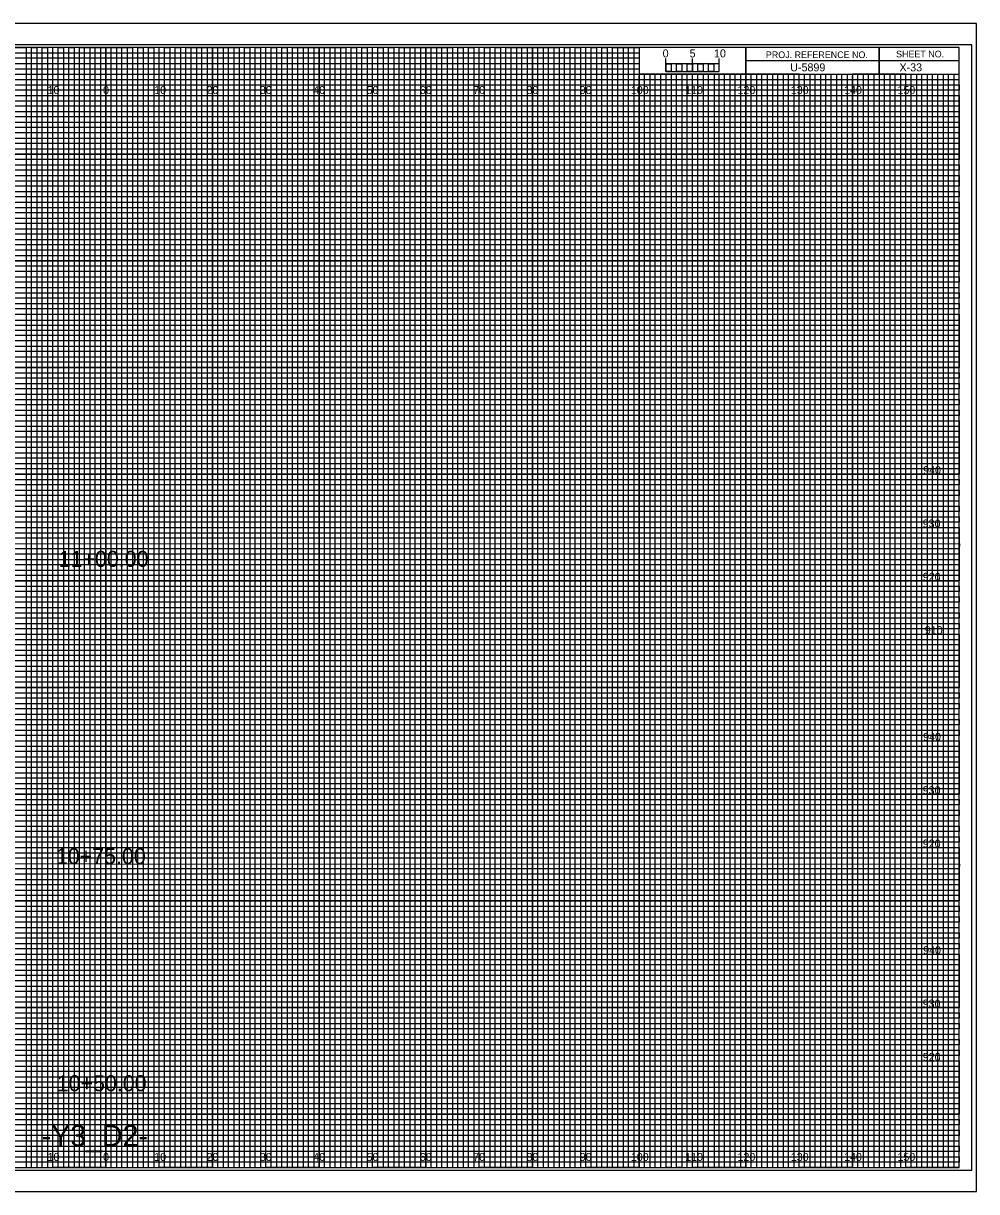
# Model space of a CAD drawing. Extents: x -13 to 323, y -4 to 214.
# Drawn here: x 144.5 to 323.3, y -4.5 to 214.5 of the extents above; entities that cross this region are included whole.
import ezdxf

# ---------------------------------------------------------------- set-up
doc = ezdxf.new("R2010")
doc.units = 0
for name, color, linetype in [('Prop XS Alignment Label', 7, 'Continuous'), ('Prop XS Bar Scale Labels', 7, 'Continuous'), ('Prop XS Elevation Labels', 7, 'Continuous'), ('Prop XS Offset Labels', 7, 'Continuous'), ('Prop XS Project Number', 7, 'Continuous'), ('Prop XS Sheet Number', 7, 'Continuous'), ('Prop XS Station Labels', 7, 'Continuous'), ('Sheet Cross Section CELL', 7, 'Continuous'), ('Sheet Cross Section Grid Major CELL', 7, 'Continuous'), ('Sheet Cross Section Grid Middle CELL', 7, 'Continuous'), ('Sheet Cross Section Grid Minor 1 CELL', 7, 'Continuous'), ('Sheet Cross Section Grid Minor 2 CELL', 7, 'Continuous'), ('Sheet Cross Section Scale CELL', 7, 'Continuous'), ('Sheet Cutting Line CELL', 7, 'Continuous'), ('Sheet DOT Grid CELL', 7, 'Continuous'), ('Sheet Plot Border Inside CELL', 7, 'Continuous'), ('Sheet Plot Border Outside CELL', 7, 'Continuous')]:
    doc.layers.add(name, color=color, linetype=linetype)

msp = doc.modelspace()

# ---------------------------------------------------------------- linework, layer by layer
at = {"layer": 'Sheet Cross Section CELL'}
for p, q in [((305, 210), (305, 205)), ((305, 205), (305, 210)), ((280, 207.5), (280, 205)), ((320, 207.49), (280, 207.49)), ((280, 205), (320, 205))]:
    msp.add_line(p, q, dxfattribs=at)
for points in [[(320, 210), (0, 210), (0, 0), (320, 0)], [(280, 210), (260, 210), (260, 205.03), (280, 205.03)], [(320, 210), (280, 210), (280, 205), (320, 205)]]:
    msp.add_lwpolyline(points, close=True, dxfattribs=at)
at = {"layer": 'Sheet Cross Section Grid Major CELL'}
for p, q in [((150, 210), (140, 210)), ((150, 0), (150, 210)), ((170, 210), (160, 210)), ((160, 210), (160, 0)), ((170, 0), (170, 210)), ((190, 210), (180, 210)), ((180, 210), (180, 0)), ((190, 0), (190, 210)), ((210, 210), (200, 210)), ((200, 210), (200, 0)), ((210, 0), (210, 210)), ((230, 210), (220, 210)), ((220, 210), (220, 0)), ((230, 0), (230, 210)), ((250, 210), (240, 210)), ((240, 210), (240, 0)), ((250, 0), (250, 210)), ((260, 210), (260, 0)), ((270, 0), (270, 205)), ((290, 205), (280, 205)), ((280, 205), (280, 0)), ((290, 0), (290, 205)), ((310, 205), (300, 205)), ((300, 205), (300, 0)), ((310, 0), (310, 205)), ((160, 0), (150, 0)), ((180, 0), (170, 0)), ((200, 0), (190, 0)), ((220, 0), (210, 0)), ((240, 0), (230, 0)), ((260, 0), (250, 0)), ((280, 0), (270, 0)), ((300, 0), (290, 0)), ((320, 0), (310, 0)), ((320, 0), (320, 0))]:
    msp.add_line(p, q, dxfattribs=at)
for points in [[(0, 200), (320, 200), (320, 190), (0, 190)], [(0, 180), (320, 180), (320, 170), (0, 170)], [(0, 160), (320, 160), (320, 150), (0, 150)], [(0, 140), (320, 140), (320, 130), (0, 130)], [(0, 120), (320, 120), (320, 110), (0, 110)], [(0, 100), (320, 100), (320, 90), (0, 90)], [(0, 80), (320, 80), (320, 70), (0, 70)], [(0, 60), (320, 60), (320, 50), (0, 50)], [(0, 40), (320, 40), (320, 30), (0, 30)], [(0, 20), (320, 20), (320, 10), (0, 10)]]:
    msp.add_lwpolyline(points, dxfattribs=at)
at = {"layer": 'Sheet Cross Section Grid Middle CELL'}
for points in [[(135, 210), (145, 210), (145, 0), (155, 0), (155, 210), (165, 210), (165, 0), (175, 0), (175, 210), (185, 210), (185, 0), (195, 0), (195, 210), (205, 210), (205, 0), (215, 0), (215, 210), (225, 210), (225, 0), (235, 0), (235, 210), (245, 210), (245, 0), (255, 0), (255, 210), (259.93, 210), (260, 210), (260, 205), (264.99, 205), (264.99, 0), (275, 0), (275, 205), (285, 205), (285, 0), (295, 0), (295, 205), (305, 205), (305, 0), (315, 0), (315, 205)], [(0, 205), (275, 205)], [(0, 185), (320, 185), (320, 195), (0, 195)], [(0, 165), (320, 165), (320, 175), (0, 175)], [(0, 145), (320, 145), (320, 155), (0, 155)], [(0, 125), (320, 125), (320, 135), (0, 135)], [(0, 105), (320, 105), (320, 115), (0, 115)], [(0, 85), (320, 85), (320, 95), (0, 95)], [(0, 65), (320, 65), (320, 75), (0, 75)], [(0, 45), (320, 45), (320, 55), (0, 55)], [(0, 25), (320, 25), (320, 35), (0, 35)], [(0, 5), (320, 5), (320, 15), (0, 15)]]:
    msp.add_lwpolyline(points, dxfattribs=at)
at = {"layer": 'Sheet Cross Section Grid Minor 1 CELL'}
for p, q in [((0, 209), (260, 209)), ((260, 209), (260, 207.98)), ((260, 207.98), (0, 207.98)), ((0, 207), (260, 207)), ((260, 205.89), (0, 205.89)), ((260, 207), (260, 205.89)), ((0, 204), (320, 204))]:
    msp.add_line(p, q, dxfattribs=at)
for points in [[(0, 203), (270, 203), (320, 203), (320, 202), (0, 202)], [(0, 201), (320, 201), (320, 199), (0, 199)], [(0, 198), (320, 198), (320, 197), (0, 196.98)], [(0, 196), (320, 196), (320, 194), (0, 194)], [(0, 193), (320, 193), (320, 192), (0, 192)], [(0, 191), (320, 191), (320, 189), (0, 189)], [(0, 188), (320, 188), (320, 187), (0, 187)], [(0, 186), (320, 186), (320, 184), (0, 184)], [(0, 183), (320, 183), (320, 182), (0, 182)], [(0, 181), (320, 181), (320, 179), (0, 179)], [(0, 178), (320, 178), (320, 177), (0, 177)], [(0, 176), (320, 176), (320, 173.95), (320, 173), (320, 172), (0, 172)], [(0, 174), (320, 174), (320, 173), (0, 173)], [(0, 171), (320, 171), (320, 169), (0, 169.03)], [(0, 169.03), (320, 169), (320, 168), (0, 168)], [(0, 167), (320, 167), (320, 166), (0, 166)], [(0, 164), (320, 164), (320, 163), (0, 163)], [(0, 162), (320, 162), (320, 161), (0, 161)], [(-0.07, 158.89), (320, 158.89), (320, 157.88), (-0.07, 157.88)], [(0, 157), (320, 157), (320, 156), (0, 156)], [(0, 154), (320, 154), (320, 153), (0, 153)], [(0, 152), (320, 152), (320, 151), (0, 151)], [(0, 149), (320, 149), (320, 148), (0, 148)], [(0, 147), (320, 147), (320, 146), (0, 146)], [(0, 144), (320, 144), (320, 143), (0, 143)], [(0, 142), (320, 142), (320, 141), (0, 141)], [(0, 139), (320, 139), (319.99, 137.98), (0, 138)], [(0, 137), (320, 137), (320, 136), (0, 136)], [(0, 134), (320, 134), (320, 133), (0, 133)], [(0, 132), (320, 132), (320, 131), (0, 131)], [(0, 129), (320, 129), (320, 128), (0, 128)], [(0, 127), (320, 127), (320, 126), (0, 126)], [(0, 124), (320, 124), (320, 123), (0, 123)], [(0, 122), (320, 122), (320, 121), (0, 121)], [(0, 119), (320, 119), (320, 118), (0, 118)], [(0, 116.99), (320.07, 116.91), (320, 116), (0, 116)], [(0, 114), (320, 114), (320, 113), (0, 113)], [(0, 112), (320, 112), (320, 111), (0, 111)], [(0, 109), (320, 109), (320, 108), (0, 108)], [(0, 107), (320, 107), (320, 106), (0, 106)], [(0, 104), (320, 104), (320, 103), (0, 103)], [(0, 102), (320, 102), (320, 101), (0, 101)], [(0, 99), (320, 99), (320, 98), (0, 98)], [(0, 97), (320, 97), (320, 96), (0, 96)], [(0, 94), (320, 94), (320, 93), (0, 93)], [(0, 92), (320, 92), (320, 91), (0, 91)], [(0, 89), (320, 89), (320, 88), (0, 88)], [(0, 87), (320, 87), (320, 86), (0, 86)], [(0, 84), (320, 84), (320, 83), (0, 83)], [(0, 82), (320, 82), (320, 81), (0, 81)], [(0, 79), (320, 79), (319.99, 77.98), (0, 78)], [(0, 77), (320, 77), (320, 76), (0, 76)], [(0, 74), (320, 74), (320, 73), (0, 73)], [(0, 72), (320, 72), (320, 71), (0, 71)], [(0, 69), (320, 69), (320, 68), (0, 68)], [(0, 67), (320, 67), (320, 66), (0, 66)], [(0, 64), (320, 64), (320, 63), (0, 63)], [(0, 62), (320, 62), (320, 61), (0, 61)], [(0, 59), (320, 59), (320, 58), (0, 58)], [(0, 56.99), (320.07, 56.91), (320, 56), (0, 56)], [(0, 54), (320, 54), (320, 53), (0, 53)], [(0, 52), (320, 52), (320, 51), (0, 51)], [(0, 49), (320, 49), (320, 48), (0, 48)], [(0, 47), (320, 47), (320, 46), (0, 46)], [(0, 44), (320, 44), (320, 43), (0, 43)], [(0, 42), (320, 42), (320, 41), (0, 41)], [(0, 39), (320, 39), (320, 38), (0, 38)], [(0, 37), (320, 37), (320, 36), (0, 36)], [(0, 34), (320, 34), (320, 33), (0, 33)], [(0, 32), (320, 32), (320, 31), (0, 31)], [(0, 29), (320, 29), (320, 28), (0, 28)], [(0, 27), (320, 27), (320, 26), (0, 26)], [(0, 24), (320, 24), (320, 23), (0, 23)], [(0, 22), (320, 22), (320, 21), (0, 21)], [(0, 19), (320, 19), (320, 18), (0, 18)], [(0, 17), (320, 17), (320, 16), (0, 16)], [(0, 14), (320, 14), (320, 13), (0, 13)], [(0, 12), (320, 12), (320, 11), (0, 11)], [(0, 9), (320, 9), (320, 8), (0, 8)], [(0, 7), (320, 7), (320, 6), (0, 6)], [(0, 4), (320, 4), (320, 3), (0, 3)], [(0, 2), (320, 2), (320, 1), (0, 1)]]:
    msp.add_lwpolyline(points, dxfattribs=at)
at = {"layer": 'Sheet Cross Section Grid Minor 2 CELL'}
for p, q in [((267, 205), (266.01, 205)), ((266.01, 205), (266.01, 0)), ((267, 0), (267, 205)), ((269, 205), (268, 205)), ((268, 205), (268, 0)), ((269, 0), (269, 205)), ((266.01, 0), (265, 0)), ((268, 0), (267, 0))]:
    msp.add_line(p, q, dxfattribs=at)
for points in [[(145, 0), (146, 0), (146, 210), (147, 210), (147, 0)], [(147, 0), (148, 0), (148, 210), (149, 210), (149, 0)], [(150, 0), (151, 0), (151, 210), (152, 210), (152, 0)], [(152, 0), (153, 0), (153, 210), (154, 210), (154, 0)], [(155, 0), (156, 0), (156, 210), (157, 210), (157, 0)], [(157, 0), (158, 0), (158, 210), (159, 210), (159, 0)], [(160, 0), (161, 0), (161, 210), (162, 210), (162, 0)], [(162, 0), (163, 0), (163, 210), (164, 210), (164, 0)], [(165, 0), (166, 0), (166, 210), (167, 210), (167, 0)], [(167, 0), (168, 0), (168, 210), (169, 210), (169, 0)], [(170, 0), (171, 0), (171, 210), (172, 210), (172, 0)], [(172, 0), (173, 0), (173, 210), (174, 210), (174, 0)], [(175, 0), (176, 0), (176, 210), (177, 210), (177, 0)], [(177, 0), (178, 0), (178, 210), (179, 210), (179, 0)], [(180, 0), (181, 0), (181, 210), (182, 210), (182, 0)], [(182, 0), (183, 0), (183, 210), (184, 210), (184, 0)], [(185, 0), (186, 0), (186, 210), (187, 210), (187, 0)], [(187, 0), (188, 0), (188, 210), (189, 210), (189, 0)], [(190, 0), (191, 0), (191, 210), (192, 210), (192, 0)], [(192, 0), (193, 0), (193, 210), (194, 210), (194, 0)], [(195, 0), (196, 0), (196, 210), (197, 210), (197, 0)], [(197, 0), (198, 0), (198, 210), (199, 210), (199, 0)], [(200, 0), (201, 0), (201, 210), (202, 210), (202, 0)], [(202, 0), (203, 0), (203, 210), (204, 210), (204, 0)], [(205, 0), (206, 0), (206, 210), (207, 210), (207, 0)], [(207, 0), (208, 0), (208, 210), (209, 210), (209, 0)], [(210, 0), (211, 0), (211, 210), (212, 210), (212, 0)], [(212, 0), (213, 0), (213, 210), (214, 210), (214, 0)], [(215, 0), (216, 0), (216, 210), (217, 210), (217, 0)], [(217, 0), (218, 0), (218, 210), (219, 210), (219, 0)], [(220, 0), (221, 0), (221, 210), (222, 210), (222, 0)], [(222, 0), (223, 0), (223, 210), (224, 210), (224, 0)], [(225, 0), (226, 0), (226, 210), (227, 210), (227, 0)], [(227, 0), (228, 0), (228, 210), (229, 210), (229, 0)], [(230, 0), (231, 0), (231, 210), (232, 210), (232, 0)], [(232, 0), (233, 0), (233, 210), (234, 210), (234, 0)], [(235, 0), (236, 0), (236, 210), (237, 210), (237, 0)], [(237, 0), (238, 0), (238, 210), (239, 210), (239, 0)], [(240, 0), (241, 0), (241, 210), (242, 210), (242, 0)], [(242, 0), (243, 0), (243, 210), (244, 210), (244, 0)], [(245, 0), (246, 0), (246, 210), (247, 210), (247, 0)], [(247, 0), (248, 0), (248, 210), (249, 210), (249, 0)], [(250, 0), (251, 0), (251, 210), (252, 210), (252, 0)], [(252, 0), (253, 0), (253, 210), (254, 210), (254, 0)], [(255, 0), (256, 0), (256, 210), (257, 210), (257, 0)], [(257, 0), (258, 0), (258, 210), (259, 210), (259, 0)], [(260, 0), (261, 0), (261, 205), (262.02, 205), (262.02, 0)], [(262, 0), (263, 0), (263, 205), (263.99, 205), (263.99, 0)], [(270, 0), (270.98, 0), (270.98, 205), (272, 205), (272, 0)], [(272, 0), (273, 0), (273, 205), (274.05, 205), (274.05, 0)], [(275, 0), (276, 0), (276, 205), (277, 205), (277, 0)], [(277, 0), (278, 0), (278, 205), (279, 205), (279, 0)], [(280, 0), (281, 0), (281, 205), (282, 205), (282, 0)], [(282, 0), (283, 0), (283, 205), (284, 205), (284, 0)], [(285, 0), (286, 0), (286, 205), (287, 205), (287, 0)], [(287, 0), (288, 0), (288, 205), (289, 205), (289, 0)], [(290, 0), (291, 0), (291, 205), (292, 205), (292, 0)], [(292, 0), (293, 0), (293, 205), (294, 205), (294, 0)], [(295, 0), (296, 0), (296, 205), (297, 205), (297, 0)], [(297, 0), (298, 0), (298, 205), (299, 205), (299, 0)], [(300, 0), (301, 0), (301, 205), (302, 205), (302, 0)], [(302, 0), (303, 0), (303, 205), (304, 205), (304, 0)], [(305, 0), (306, 0), (306, 205), (307, 205), (307, 0)], [(307, 0), (308, 0), (308, 205), (309, 205), (309, 0)], [(310, 0), (311, 0), (311, 205), (312, 205), (312, 0)], [(312, 0), (313, 0), (313, 205), (314, 205), (314, 0)], [(315, 0), (316, 0), (316, 205), (317, 205), (317, 0)], [(317, 0), (318, 0), (318, 205), (319, 205), (319, 0)]]:
    msp.add_lwpolyline(points, dxfattribs=at)
at = {"layer": 'Sheet Cross Section Scale CELL'}
for p, q in [((265, 205.49), (265, 207.9)), ((265, 206.9), (265, 207.9)), ((270, 205.49), (270, 207.9)), ((275, 205.49), (275, 207.9)), ((275, 206.9), (275, 207.9))]:
    msp.add_line(p, q, dxfattribs=at)
for points in [[(275, 206.9), (265, 206.9), (265, 205.49), (275, 205.49)], [(265, 206.9), (266, 206.9), (266, 205.49), (265, 205.49)], [(267, 206.9), (268, 206.9), (268, 205.49), (267, 205.49)], [(269, 206.9), (270, 206.9), (270, 205.49), (269, 205.49)], [(271, 206.9), (272, 206.9), (272, 205.49), (271, 205.49)], [(273, 206.9), (274, 206.9), (274, 205.49), (273, 205.49)]]:
    msp.add_lwpolyline(points, close=True, dxfattribs=at)
at = {"layer": 'Sheet Cutting Line CELL'}
for p, q in [((323.3, 214.5), (-13.4, 214.5)), ((-13.4, -4.5), (323.3, -4.5))]:
    msp.add_line(p, q, dxfattribs=at)
at = {"layer": 'Sheet DOT Grid CELL'}
for p, q in [((150, 0), (150, 210)), ((160, 0), (160, 210)), ((170, 0), (170, 210)), ((180, 0), (180, 210)), ((190, 0), (190, 210)), ((200, 0), (200, 210)), ((210, 0), (210, 210)), ((220, 0), (220, 210)), ((230, 0), (230, 210)), ((240, 0), (240, 210)), ((250, 0), (250, 210)), ((260, 0), (260, 204.69)), ((270, 0), (270, 204.69)), ((280, 0), (280, 204.69)), ((290, 0), (290, 204.69)), ((300, 0), (300, 204.69)), ((310, 0), (310, 204.69)), ((0, 200), (320, 200)), ((0, 190), (320, 190)), ((0, 180), (320, 180)), ((0, 170), (320, 170)), ((0, 160), (320, 160)), ((0, 150), (320, 150)), ((0, 140), (320, 140)), ((0, 130), (320, 130)), ((0, 120), (320, 120)), ((0, 110), (320, 110)), ((0, 100), (320, 100)), ((0, 90), (320, 90)), ((0, 80), (320, 80)), ((0, 70), (320, 70)), ((0, 60), (320, 60)), ((0, 50), (320, 50)), ((0, 40), (320, 40)), ((0, 30), (320, 30)), ((0, 20), (320, 20)), ((0, 10), (320, 10))]:
    msp.add_line(p, q, dxfattribs=at)
at = {"layer": 'Sheet Plot Border Inside CELL'}
msp.add_lwpolyline([(-10.8, -0.5), (322.4, -0.5), (322.4, 210.5), (-10.8, 210.5)], close=True, dxfattribs=at)
at = {"layer": 'Sheet Plot Border Outside CELL'}
msp.add_lwpolyline([(-13.4, -4.5), (323.3, -4.5), (323.3, 214.5), (-13.4, 214.5)], close=True, dxfattribs=at)

# ---------------------------------------------------------------- texts
at = {"layer": 'Prop XS Alignment Label'}
msp.add_text('-Y3_D2-', height=4, dxfattribs=at).set_placement((147.95, 4))
at = {"layer": 'Prop XS Bar Scale Labels'}
for s, p in [('5', (269.47, 208.12)), ('10', (274.04, 208.12))]:
    msp.add_text(s, height=1.5, dxfattribs=at).set_placement(p)
at = {"layer": 'Prop XS Elevation Labels'}
for s, p in [('940', (313.26, 130)), ('930', (313.18, 120)), ('920', (313.19, 110)), ('910', (313.57, 100)), ('940', (313.26, 80)), ('930', (313.18, 70)), ('920', (313.19, 60)), ('940', (313.26, 40)), ('930', (313.18, 30)), ('920', (313.19, 20))]:
    msp.add_text(s, height=1.5, dxfattribs=at).set_placement(p)
at = {"layer": 'Prop XS Offset Labels'}
for s, p in [('10', (149.04, 201.25)), ('0', (159.45, 201.25)), ('0', (159.45, 201.25)), ('10', (169.04, 201.25)), ('20', (178.86, 201.25)), ('30', (188.86, 201.25)), ('40', (198.86, 201.25)), ('50', (208.86, 201.25)), ('60', (218.86, 201.25)), ('70', (228.86, 201.25)), ('80', (238.86, 201.25)), ('90', (248.86, 201.25)), ('100', (258.44, 201.25)), ('110', (268.62, 201.25)), ('120', (278.44, 201.25)), ('130', (288.44, 201.25)), ('140', (298.44, 201.25)), ('150', (308.44, 201.25)), ('10', (149.04, 1.25)), ('0', (159.45, 1.25)), ('0', (159.45, 1.25)), ('10', (169.04, 1.25)), ('20', (178.86, 1.25)), ('30', (188.86, 1.25)), ('40', (198.86, 1.25)), ('50', (208.86, 1.25)), ('60', (218.86, 1.25)), ('70', (228.86, 1.25)), ('80', (238.86, 1.25)), ('90', (248.86, 1.25)), ('100', (258.44, 1.25)), ('110', (268.62, 1.25)), ('120', (278.44, 1.25)), ('130', (288.44, 1.25)), ('140', (298.44, 1.25)), ('150', (308.44, 1.25))]:
    msp.add_text(s, height=1.5, dxfattribs=at).set_placement(p)
at = {"layer": 'Prop XS Project Number'}
msp.add_text('U-5899', height=1.5, dxfattribs=at).set_placement((288.34, 205.5))
at = {"layer": 'Prop XS Sheet Number'}
msp.add_text('X-33', height=1.5, dxfattribs=at).set_placement((308.83, 205.5))
at = {"layer": 'Prop XS Station Labels'}
for s, p in [('11+00.00', (151.13, 112.61)), ('10+75.00', (150.61, 56.89)), ('10+50.00', (150.77, 14.32))]:
    msp.add_text(s, height=3, dxfattribs=at).set_placement(p)
at = {"layer": 'Sheet Cross Section CELL'}
for s, p in [('PROJ. REFERENCE NO.', (283.77, 207.99)), ('SHEET NO.', (308.19, 208.12))]:
    msp.add_text(s, height=1.25, dxfattribs=at).set_placement(p)
at = {"layer": 'Sheet Cross Section Scale CELL'}
msp.add_text('0', height=1.5, dxfattribs=at).set_placement((264.41, 208.12))

doc.saveas('drawing.dxf')
